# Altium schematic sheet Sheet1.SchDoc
size A4; CompanyName: Ultimaker; Revision: rev. 2.1.2
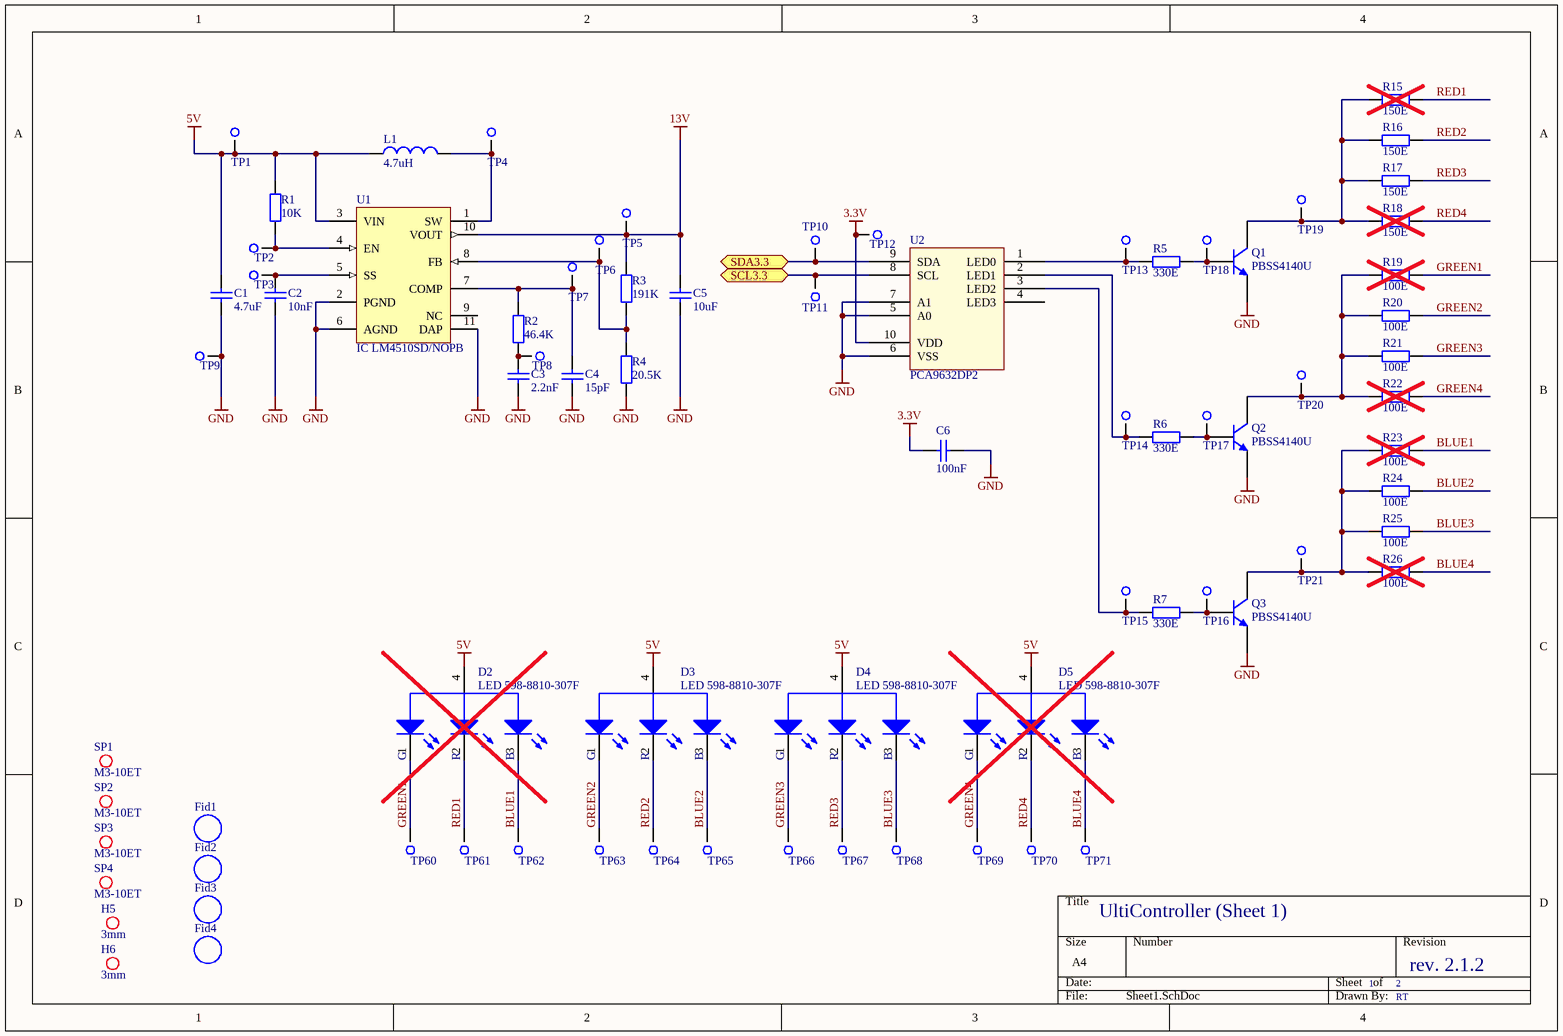
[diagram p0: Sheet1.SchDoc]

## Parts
C1  4.7uF  [C1206 (3216)]
C2  10nF  [C0805 (2012)]
C3  2.2nF  [C0805 (2012)]
C4  15pF  [C0805 (2012)]
C5  10uF  [C1206 (3216)]
C6  100nF  [C0805 (2012)]
D2  LED 598-8810-307F  [LED SMD  598-8810-307F]  (no BOM)
D3  LED 598-8810-307F  [LED SMD  598-8810-307F]
D4  LED 598-8810-307F  [LED SMD  598-8810-307F]
D5  LED 598-8810-307F  [LED SMD  598-8810-307F]  (no BOM)
Fid1  Fiducial  [Fiducial 1,5mm]  (value not drawn)  (no BOM)
Fid2  Fiducial  [Fiducial 1,5mm]  (value not drawn)  (no BOM)
Fid3  Fiducial  [Fiducial 1,5mm]  (value not drawn)  (no BOM)
Fid4  Fiducial  [Fiducial 1,5mm]  (value not drawn)  (no BOM)
H5  3mm  [Mounting Hole 3mm PTH]  (no BOM)
H6  3mm  [Mounting Hole 3mm PTH]  (no BOM)
L1  4.7uH  [Inductor MCSDC0604]
Q1  PBSS4140U  [IC SOT323]
Q2  PBSS4140U  [IC SOT323]
Q3  PBSS4140U  [IC SOT323]
R1  10K  [R0805 (2012)]
R2  46.4K  [R0805 (2012)]
R3  191K  [R0805 (2012)]
R4  20.5K  [R0805 (2012)]
R5  330E  [R0805 (2012)]
R6  330E  [R0805 (2012)]
R7  330E  [R0805 (2012)]
R15  150E  [R0805 (2012)]  (no BOM)
R16  150E  [R0805 (2012)]
R17  150E  [R0805 (2012)]
R18  150E  [R0805 (2012)]  (no BOM)
R19  100E  [R0805 (2012)]  (no BOM)
R20  100E  [R0805 (2012)]
R21  100E  [R0805 (2012)]
R22  100E  [R0805 (2012)]  (no BOM)
R23  100E  [R0805 (2012)]  (no BOM)
R24  100E  [R0805 (2012)]
R25  100E  [R0805 (2012)]
R26  100E  [R0805 (2012)]  (no BOM)
SP1  M3-10ET  [Spacer M3-10ET]
SP2  M3-10ET  [Spacer M3-10ET]
SP3  M3-10ET  [Spacer M3-10ET]
SP4  M3-10ET  [Spacer M3-10ET]
TP1  2mm  [TESTPOINT 2mm]  (value not drawn)  (no BOM)
TP2  2mm  [TESTPOINT 2mm]  (value not drawn)  (no BOM)
TP3  2mm  [TESTPOINT 2mm]  (value not drawn)  (no BOM)
TP4  2mm  [TESTPOINT 2mm]  (value not drawn)  (no BOM)
TP5  2mm  [TESTPOINT 2mm]  (value not drawn)  (no BOM)
TP6  2mm  [TESTPOINT 2mm]  (value not drawn)  (no BOM)
TP7  2mm  [TESTPOINT 2mm]  (value not drawn)  (no BOM)
TP8  2mm  [TESTPOINT 2mm]  (value not drawn)  (no BOM)
TP9  2mm  [TESTPOINT 2mm]  (value not drawn)  (no BOM)
TP10  2mm  [TESTPOINT 2mm]  (value not drawn)  (no BOM)
TP11  2mm  [TESTPOINT 2mm]  (value not drawn)  (no BOM)
TP12  2mm  [TESTPOINT 2mm]  (value not drawn)  (no BOM)
TP13  2mm  [TESTPOINT 2mm]  (value not drawn)  (no BOM)
TP14  2mm  [TESTPOINT 2mm]  (value not drawn)  (no BOM)
TP15  2mm  [TESTPOINT 2mm]  (value not drawn)  (no BOM)
TP16  2mm  [TESTPOINT 2mm]  (value not drawn)  (no BOM)
TP17  2mm  [TESTPOINT 2mm]  (value not drawn)  (no BOM)
TP18  2mm  [TESTPOINT 2mm]  (value not drawn)  (no BOM)
TP19  2mm  [TESTPOINT 2mm]  (value not drawn)  (no BOM)
TP20  2mm  [TESTPOINT 2mm]  (value not drawn)  (no BOM)
TP21  2mm  [TESTPOINT 2mm]  (value not drawn)  (no BOM)
TP60  2mm  [TESTPOINT 2mm]  (value not drawn)  (no BOM)
TP61  2mm  [TESTPOINT 2mm]  (value not drawn)  (no BOM)
TP62  2mm  [TESTPOINT 2mm]  (value not drawn)  (no BOM)
TP63  2mm  [TESTPOINT 2mm]  (value not drawn)  (no BOM)
TP64  2mm  [TESTPOINT 2mm]  (value not drawn)  (no BOM)
TP65  2mm  [TESTPOINT 2mm]  (value not drawn)  (no BOM)
TP66  2mm  [TESTPOINT 2mm]  (value not drawn)  (no BOM)
TP67  2mm  [TESTPOINT 2mm]  (value not drawn)  (no BOM)
TP68  2mm  [TESTPOINT 2mm]  (value not drawn)  (no BOM)
TP69  2mm  [TESTPOINT 2mm]  (value not drawn)  (no BOM)
TP70  2mm  [TESTPOINT 2mm]  (value not drawn)  (no BOM)
TP71  2mm  [TESTPOINT 2mm]  (value not drawn)  (no BOM)
U1  IC LM4510SD/NOPB  [IC SDA10A]
U2  PCA9632DP2  [IC TSSOP-10]

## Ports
SCL3.3 (bidir), SDA3.3 (bidir)

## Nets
3.3V: C6.1 TP12.1 U2.10(VDD)
5V: C1.2 D2.4 D3.4 D4.4 D5.4 L1.1 R1.2 TP1.1 U1.3(VIN)
13V: C5.2 R3.2 TP5.1 U1.10(VOUT)
GND: C1.1 C2.1 C3.1 C4.1 C5.1 C6.2 Q1.2(E) Q2.2(E) Q3.2(E) R4.1 TP9.1 U1.2(PGND) U1.6(AGND) U1.11(DAP) U2.5(A0) U2.6(VSS) U2.7(A1)
BLUE1: D2.3 R23.2 TP62.1
BLUE2: D3.3 R24.2 TP65.1
BLUE3: D4.3 R25.2 TP68.1
BLUE4: D5.3 R26.2 TP71.1
GREEN1: D2.1 R19.2 TP60.1
GREEN2: D3.1 R20.2 TP63.1
GREEN3: D4.1 R21.2 TP66.1
GREEN4: D5.1 R22.2 TP69.1
RED1: D2.2 R15.2 TP61.1
RED2: D3.2 R16.2 TP64.1
RED3: D4.2 R17.2 TP67.1
RED4: D5.2 R18.2 TP70.1
SCL3.3: TP11.1 U2.8(SCL) ; port SCL3.3
SDA3.3: TP10.1 U2.9(SDA) ; port SDA3.3
NetC2_2: C2.2 TP3.1 U1.5(SS)
NetC3_2: C3.2 R2.1 TP8.1
NetC4_2: C4.2 R2.2 TP7.1 U1.7(COMP)
NetL1_2: L1.2 TP4.1 U1.1(SW)
NetQ1_1: Q1.1(B) R5.2 TP18.1
NetQ1_3: Q1.3(C) R15.1 R16.1 R17.1 R18.1 TP19.1
NetQ2_1: Q2.1(B) R6.2 TP17.1
NetQ2_3: Q2.3(C) R19.1 R20.1 R21.1 R22.1 TP20.1
NetQ3_1: Q3.1(B) R7.2 TP16.1
NetQ3_3: Q3.3(C) R23.1 R24.1 R25.1 R26.1 TP21.1
NetR1_1: R1.1 TP2.1 U1.4(EN)
NetR3_1: R3.1 R4.2 TP6.1 U1.8(FB)
NetR5_1: R5.1 TP13.1 U2.1(LED0)
NetR6_1: R6.1 TP14.1 U2.2(LED1)
NetR7_1: R7.1 TP15.1 U2.3(LED2)

Not connected (* = marked no-connect by the designer): U1 9(NC); U2 4(LED3)

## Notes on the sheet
- UltiController (Sheet 1)
- 1
- 2
- rev. 2.1.2
- RT

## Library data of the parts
C1 = Cap 4.7uF X7R 1206: Cap 4.7uF 1206 X7R 10% 25V; Mfg: TDK; Mfg code: C3216X7R1E475K160AC
C2 = Cap 10nF X7R 0805: Cap 10nF X7R 0805 10% 100V; Mfg: AVX; Mfg code: 08051C103K4Z2A
C3 = Cap 2.2nF X7R 0805: Cap 2.2nF X7R 0805 10% 100V; Mfg: KEMET; Mfg code: C0805F222K1RACAUTO
C4 = Cap 15pF NPO 0805: Cap 15pF NPO 0805 5% 100V; Mfg: AVX; Mfg code: 08051A150JAT2A
C5 = Cap 10uF X7R 1206: Cap 10uF 1206 X7R 10% 25V; Mfg: KEMET; Mfg code: C1206C106K3RAC TU
C6 = Cap 100nF X7R 0805: Cap 100nF X7R 0805 10% 100V; Mfg: AVX; Mfg code: 08051C104K4T2A
D2-D5 = LED 598-8810-307F: LED MULTICOLOR RED/GRN/BLUE 1208; Mfg: DIALIGHT; Bestel grote: 1; Prijs: 2.26
Fid1-Fid4 = Fiducial: Remarks: Not a component
H5 H6 = Mounting Hole 3mm PTH: Remarks: Not a component
L1 = Inductor 4.7uH SMD: Mfg: MULTICOMP; Mfg code: MCSDC0604-4R7MU
Q1-Q3 = NPN PBSS4140U: NPN PBSS4140U SOT-323 1A; Mfg: NXP
R1 = Res 10K 0805: Res 10K 0805 1% 100mW; Mfg: MULTICOMP; Mfg code: MC 0.1W 0805 1% 10K
R2 = Res 46.4K 0805: Res 46.4K 0805 1% 100mW; Mfg: MULTICOMP; Mfg code: MC0.1W08051%46K4
R3 = Res 191K 0805: Res 191K 0805 1% 125mW; Mfg: VISHAY DRALORIC; Mfg code: CRCW0805191KFKEA
R4 = Res 20.5K 0805: Res 20.5K 0805 1% 100mW; Mfg: MULTICOMP; Mfg code: MC0.1W08051%20K5
R5-R7 = Res 330E 0805: Res 330E 0805 1% 100mW; Mfg: MULTICOMP; Mfg code: MC 0.1W 0805 1% 330R
R15-R18 = Res 150E 0805: Res 150E 0805 1% 125mW; Faber ItemCode: 31224600; Mfg: YAGEO; Mfg code: 2322 734 61501; Faber Artikelomschrijving: RES 150E 1% 0,125W 0805; Bestel grote: 5000; Prijs: 0,0012
R19-R26 = Res 100E 0805: Res 100E 0805 1% 125mW; Faber ItemCode: 31560100; Mfg: YAGEO; Mfg code: WRC31022/ RC0805FR-07100RL; Faber Artikelomschrijving: RES 100E 1% 0,125W 0805; Bestel grote: 5000; Prijs: 0,0009
SP1-SP4 = Spacer M3-10ET: Spacer SMTSO-M3-10ET; Faber ItemCode: 36462900; Mfg: PEM; Faber Artikelomschrijving: MOER-SMD SMTSO-M3-10ET  PEM; Bestel grote: 300; Prijs: 0.4311
TP1-TP21 TP60-TP71 = Testpoint, 2mm, round: Remarks: Not a component
U1 = IC LM4510SD/NOPB: IC Synchronous Step-Up DC/DC Converter with True Shutdown Isolation, 10-pin LLP, Pb-Free; Faber ItemCode: 36966700; Mfg: TEXAS INSTRUMENTS; Faber Artikelomschrijving: IC LM4510SD/NOPB LLP-10 TI; Bestel grote: 1; Prijs: 1,10
U2 = IC PCA9632: IC LED DRIVER RGBA; Faber ItemCode: 36966800; Mfg: NXP; Faber Artikelomschrijving: IC PCA9632DP2 TSSOP-10 NXP; Bestel grote: 1000; Prijs: 1,0876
